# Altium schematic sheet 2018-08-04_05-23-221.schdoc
size 546 x 220 mm; SheetNumber: 1; SheetTotal: 1
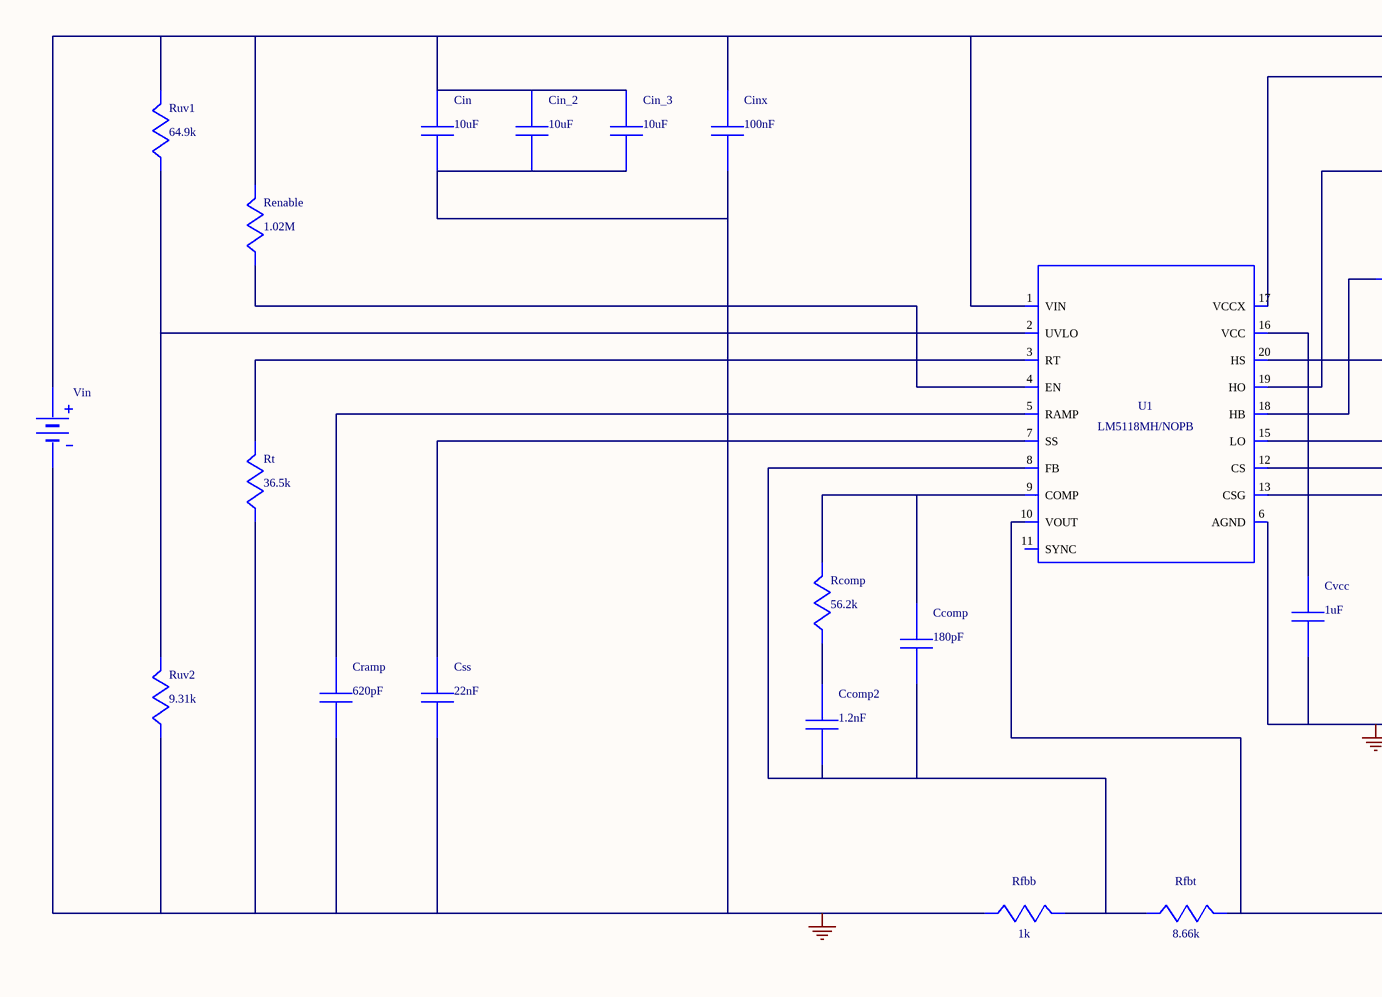
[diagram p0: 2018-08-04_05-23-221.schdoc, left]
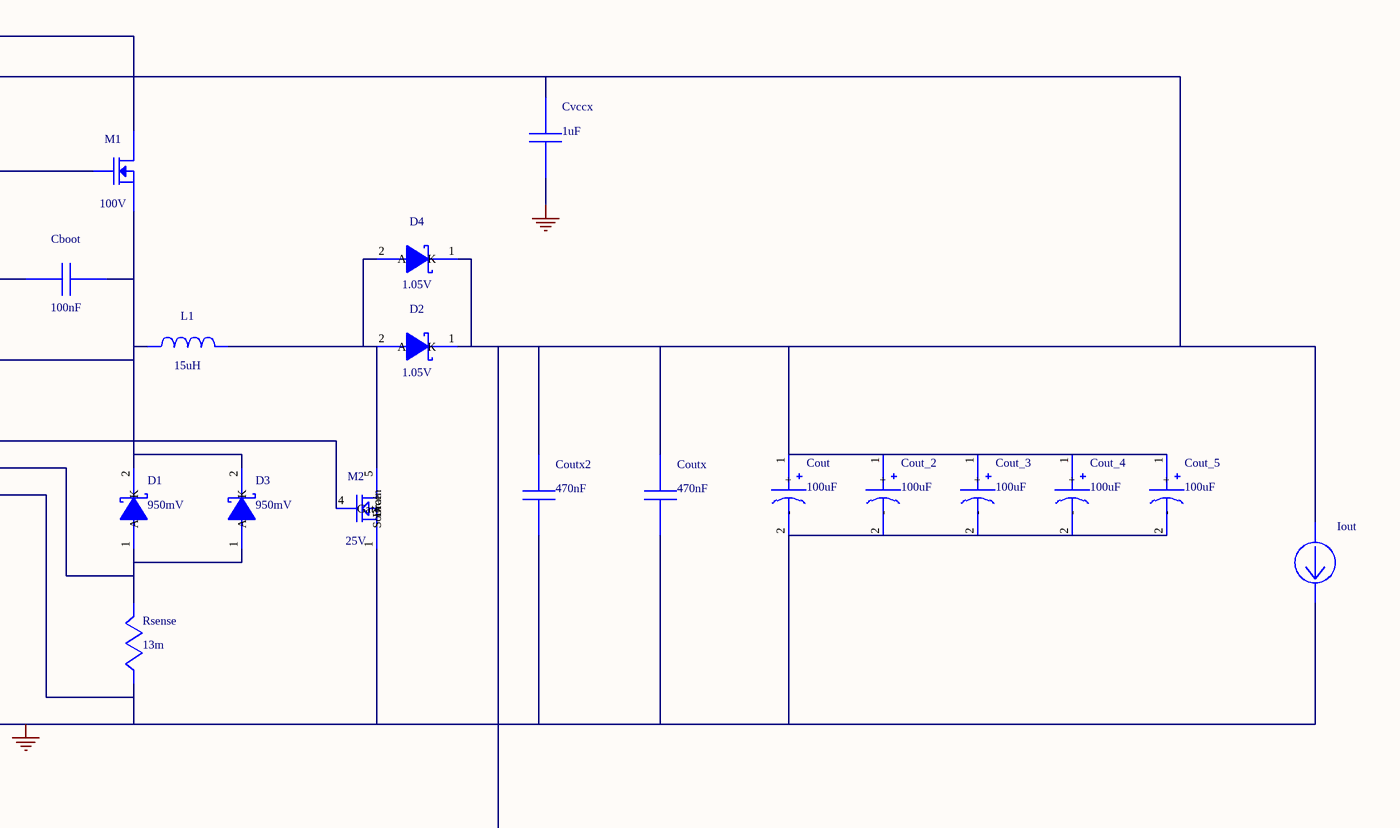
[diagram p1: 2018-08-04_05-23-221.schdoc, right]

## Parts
Cboot  value 100nF  (hidden comment: 08053C104JAZ2A)
Ccomp  value 180pF  (hidden comment: CL05C181JB5NNNC)
Ccomp2  value 1.2nF  (hidden comment: CL10C122JB8NNNC)
Cin  value 10uF  (hidden comment: C5750X7S2A106K230KB)
Cin_2  value 10uF  (hidden comment: C5750X7S2A106K230KB)
Cin_3  value 10uF  (hidden comment: C5750X7S2A106K230KB)
Cinx  value 100nF  (hidden comment: CGA4J2X7R2A104K125AA)
Cout  value 100uF  (hidden comment: EEHZA1H101P)
Cout_2  value 100uF  (hidden comment: EEHZA1H101P)
Cout_3  value 100uF  (hidden comment: EEHZA1H101P)
Cout_4  value 100uF  (hidden comment: EEHZA1H101P)
Cout_5  value 100uF  (hidden comment: EEHZA1H101P)
Coutx  value 470nF  (hidden comment: EMK212B7474KD-T)
Coutx2  value 470nF  (hidden comment: EMK212B7474KD-T)
Cramp  value 620pF  (hidden comment: CL21C621JBCNNNC)
Css  value 22nF  (hidden comment: C2012C0G1H223K125AA)
Cvcc  value 1uF  (hidden comment: TMK212B7105KG-T)
Cvccx  value 1uF  (hidden comment: TMK212B7105KG-T)
D1  value 950mV  (hidden comment: SBRD10200TR)
D2  value 1.05V  (hidden comment: SB10150TA)
D3  value 950mV  (hidden comment: SBRD10200TR)
D4  value 1.05V  (hidden comment: SB10150TA)
Iout  WB_CURRENT_LOAD  (value not drawn)
L1  value 15uH  (hidden comment: SER2915L-153KL)
M1  value 100V  (hidden comment: CSD19534Q5A)
M2  value 25V  (hidden comment: CSD16327Q3)
Rcomp  value 56.2k  (hidden comment: RC0201FR-0756K2L)
Renable  value 1.02M  (hidden comment: CRCW04021M02FKED)
Rfbb  value 1k  (hidden comment: ERJ-6ENF1001V)
Rfbt  value 8.66k  (hidden comment: ERJ-6ENF8661V)
Rsense  value 13m  (hidden comment: PRL1632-R013-F-T1)
Rt  value 36.5k  (hidden comment: RC0201FR-0736K5L)
Ruv1  value 64.9k  (hidden comment: CRCW040264K9FKED)
Ruv2  value 9.31k  (hidden comment: CRCW04029K31FKED)
U1  LM5118MH/NOPB
Vin  WB_BATTERY  (value not drawn)

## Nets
0: Cin.2 Cin_2.2 Cin_3.2 Cinx.2 Cout.2(-) Cout_2.2(-) Cout_3.2(-) Cout_4.2(-) Cout_5.2(-) Coutx.2 Coutx2.2 Cramp.2 Css.2 Cvcc.2 Cvccx.1 Iout.2(-) M2.1(Source) M2.2(Source) M2.3(Source) Rfbb.2 Rsense.2 Rt.2 Ruv2.2 U1.6(AGND) U1.13(CSG) U1.14(PGND) U1.21(EP) Vin.2(-)
NetCboot_1: Cboot.1 D1.2(K) D3.2(K) L1.2 M1.1(Source) M1.2(Source) M1.3(Source) U1.20(HS)
NetCboot_2: Cboot.2 U1.18(HB)
NetCcomp2_1: Ccomp2.1 Rcomp.2
NetCcomp_1: Ccomp.1 Rcomp.1 U1.9(COMP)
NetCcomp_2: Ccomp.2 Ccomp2.2 Rfbb.1 Rfbt.2 U1.8(FB)
NetCin_1: Cin.1 Cin_2.1 Cin_3.1 Cinx.1 M1.5(Drain) M1.6(Drain) M1.7(Drain) M1.8(Drain) M1.9(Drain) Renable.1 Ruv1.1 U1.1(VIN) Vin.1(+)
NetCout_1: Cout.1(+) Cout_2.1(+) Cout_3.1(+) Cout_4.1(+) Cout_5.1(+) Coutx.1 Coutx2.1 Cvccx.2 D2.1(K) D4.1(K) Iout.1(+) Rfbt.1 U1.10(VOUT) U1.17(VCCX)
NetCramp_1: Cramp.1 U1.5(RAMP)
NetCss_1: Css.1 U1.7(SS)
NetCvcc_1: Cvcc.1 U1.16(VCC)
NetD1_1: D1.1(A) D1.3(A) D3.1(A) D3.3(A) Rsense.1 U1.12(CS)
NetD2_2: D2.2(A) D4.2(A) L1.1 M2.5(Drain) M2.6(Drain) M2.7(Drain) M2.8(Drain) M2.9(Drain)
NetM1_4: M1.4(Gate) U1.19(HO)
NetM2_4: M2.4(Gate) U1.15(LO)
NetRenable_2: Renable.2 U1.4(EN)
NetRt_1: Rt.1 U1.3(RT)
NetRuv1_2: Ruv1.2 Ruv2.1 U1.2(UVLO)

Not connected (* = marked no-connect by the designer): U1 11(SYNC)

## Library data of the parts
Cboot = 08053C104JAZ2A: Manufacturer Name: AVX
Ccomp = CL05C181JB5NNNC: Manufacturer Name: Samsung Electro-Mechanics
Ccomp2 = CL10C122JB8NNNC: Manufacturer Name: Samsung Electro-Mechanics
Cin Cin_2 Cin_3 = C5750X7S2A106K230KB: C5750X7S2A106K23; Manufacturer Name: TDK
Cinx = CGA4J2X7R2A104K125AA: CGA4J2X7R2A104K1; Manufacturer Name: TDK
Cout Cout_2-Cout_5 = EEHZA1H101P: Manufacturer Name: Panasonic
Coutx Coutx2 = EMK212B7474KD-T: Manufacturer Name: Taiyo Yuden
Cramp = CL21C621JBCNNNC: Manufacturer Name: Samsung Electro-Mechanics
Css = C2012C0G1H223K125AA: C2012C0G1H223K12; Manufacturer Name: TDK
Cvcc Cvccx = TMK212B7105KG-T: Manufacturer Name: Taiyo Yuden
D1 D3 = SBRD10200TR: Manufacturer Name: SMC Diode Solutions
D2 D4 = SB10150TA: Manufacturer Name: SMC Diode Solutions
L1 = SER2915L-153KL: Manufacturer Name: Coilcraft
M1 = CSD19534Q5A: Manufacturer Name: Texas Instruments
M2 = CSD16327Q3: Manufacturer Name: Texas Instruments
Rcomp = RC0201FR-0756K2L: Manufacturer Name: Yageo
Renable = CRCW04021M02FKED: Manufacturer Name: Vishay-Dale
Rfbb = ERJ-6ENF1001V: Manufacturer Name: Panasonic
Rfbt = ERJ-6ENF8661V: Manufacturer Name: Panasonic
Rsense = PRL1632-R013-F-T1: PRL1632-R013-F-T; Manufacturer Name: Susumu Co Ltd
Rt = RC0201FR-0736K5L: Manufacturer Name: Yageo
Ruv1 = CRCW040264K9FKED: Manufacturer Name: Vishay-Dale
Ruv2 = CRCW04029K31FKED: Manufacturer Name: Vishay-Dale
U1 = LM5118MH/NOPB: Manufacturer Name: Texas Instruments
